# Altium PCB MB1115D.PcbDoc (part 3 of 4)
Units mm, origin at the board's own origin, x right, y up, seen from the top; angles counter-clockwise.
Board outline 66 x 97 mm, 2 copper layers (TOP, Bottom), stack 1.535 mm thick; 198 components, 186 nets, 760 pads, 493 vias.
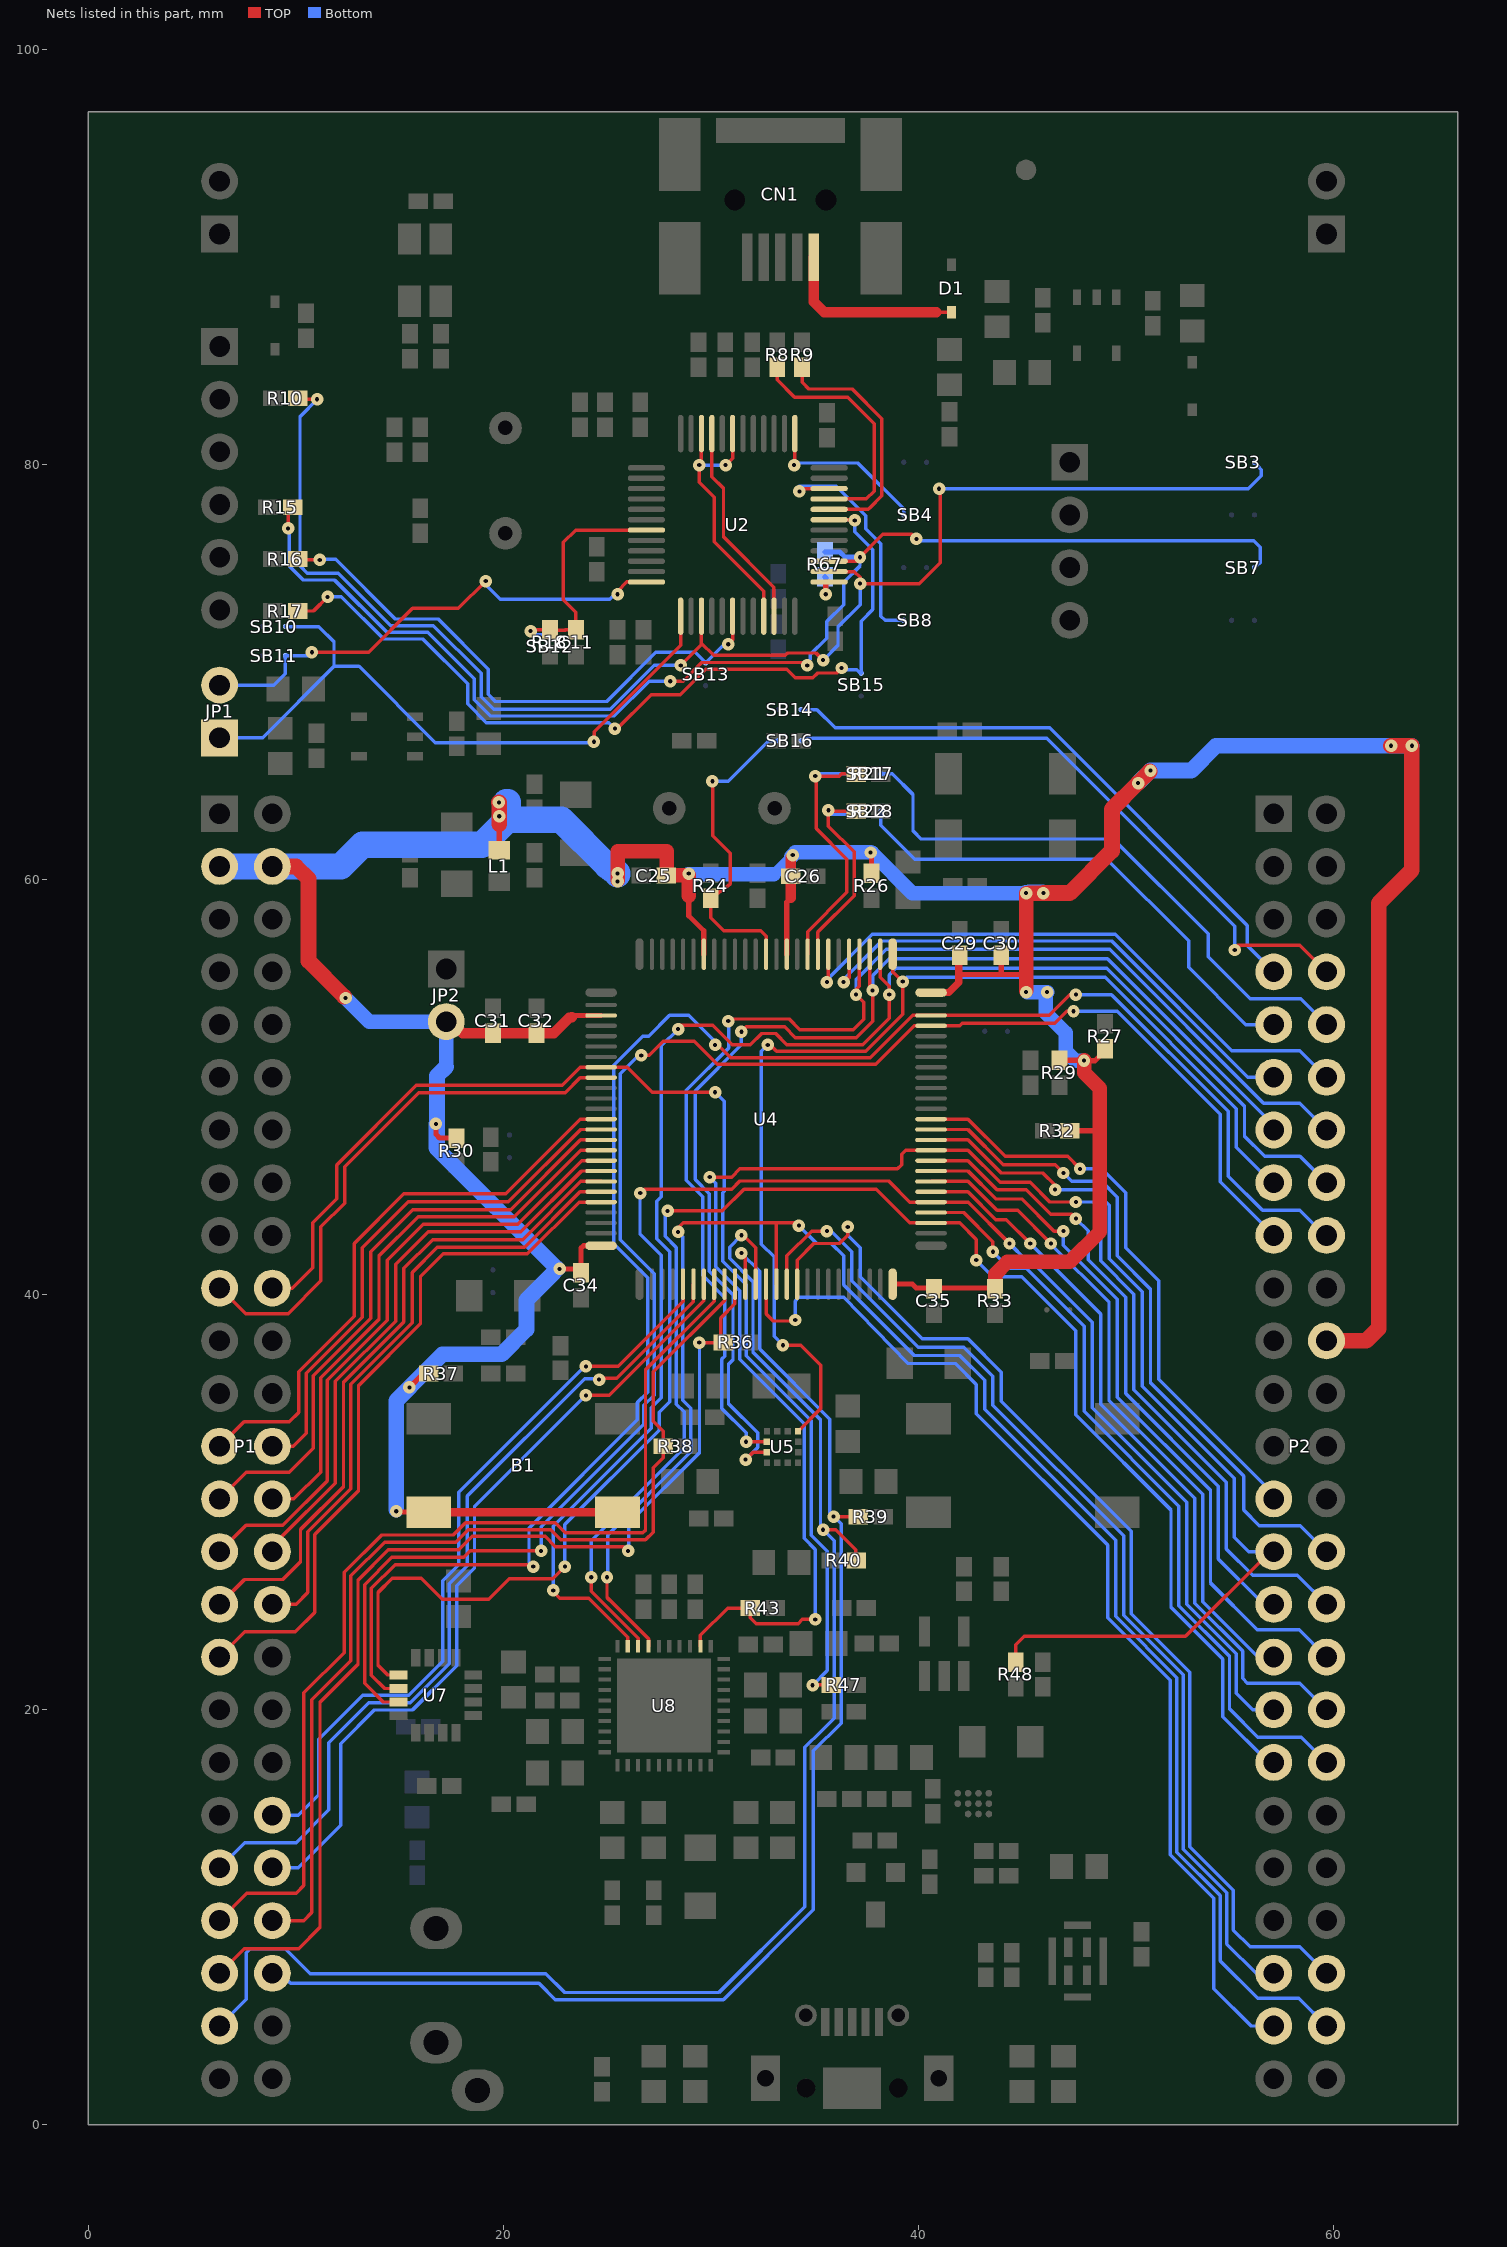
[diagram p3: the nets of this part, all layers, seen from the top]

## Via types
v1: diameter 0.6, hole 0.2, TOP to Bottom, tented both sides, 492 vias
v2: diameter 0.6, hole 0.2, TOP to Bottom, tented bottom, 1 vias

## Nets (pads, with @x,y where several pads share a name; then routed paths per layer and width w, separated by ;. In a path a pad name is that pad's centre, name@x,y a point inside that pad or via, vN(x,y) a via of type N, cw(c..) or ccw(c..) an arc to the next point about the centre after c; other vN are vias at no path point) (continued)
PC4: P1.20 R47.2 U4.33 | length 60.6
  TOP w0.165: P1.20@8.87,40.32 9.823,40.32 10.811,41.309 10.811,43.469 11.969,44.626 11.969,46.251 15.804,50.086 22.84,50.086 23.716,50.962 U4.33@24.714,50.962 25.965,50.962 27.171,49.756 v1(30.206,49.756) ; v1(34.905,21.181) 34.905,21.2 R47.2@35.8,21.2
  Bottom w0.165: v1(30.206,49.756) 30.219,49.756 30.651,49.324 30.651,44.981 30.574,44.905 30.574,41.615 31.717,40.472 31.717,37.056 34.842,33.932 34.842,28.407 35.616,27.633 35.616,21.892 v1(34.905,21.181)
PC5: P1.19 U4.34 | length 26.2
  TOP w0.165: P1.19@6.33,40.32 7.579,39.088 9.632,39.088 11.211,40.667 11.211,43.269 12.35,44.408 12.35,46.175 15.919,49.743 22.98,49.743 23.698,50.462 U4.34@24.714,50.462
PC6: P2.47 U4.63 | length 52
  TOP w0.165: U4.63@32.664,40.512 32.664,39.071 33,38.735 34.018,38.735 v1(34.067,38.783)
  Bottom w0.165: v1(34.067,38.783) 34.067,39.698 34.24,39.871 36.398,39.871 39.5,36.7 41.796,36.672 42.795,35.673 42.795,34.274 49.129,27.94 49.129,24.433 52.139,21.423 52.139,13.015 54.234,10.919 54.234,6.563 56.038,4.76 P2.47@57.13,4.76
PC7: P2.48 U4.64 U8.37 | length 84.1
  TOP w0.165: v1(24.999,26.388) 24.999,25.41 25.266,25.143 27,23.409 27,23.251 U8.37@27,23.07 ; v1(28.428,43.025) 28.225,43.025 28.669,43.469 33.164,43.469 ; U4.64@33.164,40.512 33.164,43.469 ; v1(34.245,43.33) 34.105,43.469 33.164,43.469
  Bottom w0.165: v1(24.999,26.388) 24.999,26.515 25.024,26.54 25.024,28.42 29.038,32.433 29.038,34.529 28.657,34.91 28.657,42.796 v1(28.428,43.025) ; v1(34.245,43.33) 35.105,42.469 35.799,42.469 36.398,41.87 36.398,40.471 39.797,37.072 41.995,37.072 43.195,35.873 43.195,34.474 49.51,28.158 49.51,24.498 52.456,21.551 52.456,13.143 54.552,11.047 54.552,7.891 56.355,6.088 58.342,6.088 P2.48@59.67,4.76
PC8: P2.45 U4.65 | length 50.4
  TOP w0.165: U4.65@33.664,40.512 33.664,41.87 34.863,43.069 v1(35.599,43.069)
  Bottom w0.165: v1(35.599,43.069) 35.799,43.069 36.798,42.07 36.798,40.67 39.996,37.472 42.195,37.472 43.595,36.073 43.595,34.674 49.891,28.377 49.891,24.562 52.774,21.679 52.774,13.271 54.869,11.175 54.869,8.71 56.279,7.3 P2.45@57.13,7.3
PC9: P2.46 U4.66 | length 52.7
  TOP w0.165: U4.66@34.164,40.512 34.164,41.67 34.963,42.469 36.198,42.469 36.598,42.869 v1(36.598,43.269)
  Bottom w0.165: v1(36.598,43.269) 36.598,42.869 37.198,42.27 37.198,40.87 40.196,37.872 42.395,37.872 43.994,36.273 43.994,34.873 50.272,28.596 50.272,24.627 53.091,21.807 53.091,13.399 55.187,11.303 55.187,9.384 55.988,8.583 58.387,8.583 P2.46@59.67,7.3
PC10: P2.37 U4.78 U8.38 | length 72.6
  TOP w0.165: v1(24.237,26.388) 24.237,25.715 26.5,23.452 U8.38@26.5,23.07 ; v1(27.92,44.041) 30.56,44.041 31.601,45.082 37.976,45.082 39.597,43.462 U4.78@40.614,43.462 41.995,43.462 42.795,42.662 v1(42.795,41.67)
  Bottom w0.165: v1(24.237,26.388) 24.237,28.153 25.075,28.991 28.72,32.636 28.72,34.351 28.339,34.732 28.339,42.276 27.806,42.809 27.806,43.965 27.882,44.041 v1(27.92,44.041) ; v1(42.795,41.67) 43.595,40.87 44.994,40.87 47.593,38.272 47.593,34.211 52.177,29.627 52.177,24.949 54.679,22.447 54.679,19.657 56.876,17.46 P2.37@57.13,17.46
PC11: P2.38 U4.79 | length 37
  TOP w0.165: U4.79@40.614,43.962 42.195,43.962 43.595,42.563 v1(43.595,42.07)
  Bottom w0.165: v1(43.595,42.07) 44.394,41.27 45.194,41.27 47.992,38.472 47.992,34.383 52.558,29.817 52.558,25.013 54.996,22.575 54.996,20.053 56.368,18.682 58.448,18.682 P2.38@59.67,17.46
PC12: P2.35 U4.80 U8.39 | length 74.5
  TOP w0.165: v1(22.405,25.753) 22.405,25.678 22.711,25.372 24.123,25.372 26,23.495 U8.39@26,23.07 ; v1(26.6,44.9) 26.782,45.082 31.001,45.082 31.401,45.482 38.576,45.482 39.597,44.462 U4.80@40.614,44.462 42.402,44.462 v1(44.394,42.469)
  Bottom w0.165: v1(22.405,25.753) 22.405,28.836 27.133,33.563 27.133,34.554 27.615,35.037 27.615,41.907 26.587,42.936 26.587,44.887 v1(26.6,44.9) ; v1(44.394,42.469) 45.194,41.67 45.394,41.67 48.392,38.671 48.392,34.554 52.939,30.008 52.939,25.078 55.314,22.703 55.314,20.8 56.114,20 P2.35@57.13,20
PC13: P2.12 U4.7 | length 29.3
  TOP w0.165: v1(35.599,55.063) 35.664,55.128 U4.7@35.664,56.412
  Bottom w0.165: v1(35.599,55.063) 35.599,55.174 37.788,57.363 49.497,57.363 55.098,51.763 58.387,51.763 P2.12@59.67,50.48
PC14: P2.9 SB18.2 | length 24.3
  Bottom w0.165: SB18.2@38.2,63.3 38.2,62.615 39.82,60.995 49.091,60.995 53.028,57.058 53.028,55.78 55.788,53.02 P2.9@57.13,53.02
PC14-OSC32_IN: R22.1 SB18.1 U4.8 | length 11.2
  TOP w0.165: U4.8@35.164,56.412 35.164,57.482 36.912,59.23 36.912,61.338 35.667,62.583 v1(35.667,63.345) 35.712,63.3 R22.1@37,63.3
  Bottom w0.165: v1(35.667,63.345) 35.667,63.154 36.954,63.154 SB18.1@37.1,63.3
PC15: P2.10 SB17.2 | length 28.1
  Bottom w0.165: SB17.2@38.2,65.1 38.751,65.1 39.744,64.107 39.744,62.367 40.15,61.961 49.408,61.961 53.968,57.401 53.968,56.284 55.988,54.263 58.427,54.263 P2.10@59.67,53.02
PC15-OSC32_OUT: R21.1 SB17.1 U4.9 | length 14.2
  TOP w0.165: U4.9@34.664,56.412 34.664,57.503 36.556,59.395 36.556,60.995 35.083,62.469 v1@35.083,64.983 ; v1(35.032,64.996) 35.083,64.996 v1@35.083,64.983 ; R21.1@37,65.1 36.298,65.1 36.181,64.983 v1@35.083,64.983
  Bottom w0.165: v1(35.032,64.996) 35.032,65.1 SB17.1@37.1,65.1
PD0: P2.36 U4.81 | length 35.7
  TOP w0.165: U4.81@40.614,44.962 42.395,44.962 43.741,43.616 44.247,43.616 v1(45.394,42.469)
  Bottom w0.165: v1(45.394,42.469) 48.792,39.071 48.792,34.726 53.32,30.198 53.32,25.142 55.631,22.831 55.631,21.51 55.86,21.282 58.388,21.282 P2.36@59.67,20
PD1: P2.33 U4.82 | length 31.8
  TOP w0.165: U4.82@40.614,45.462 42.395,45.462 43.791,44.066 44.797,44.066 v1(46.393,42.469)
  Bottom w0.165: v1(46.393,42.469) 46.393,42.433 49.192,39.635 49.192,34.898 53.701,30.389 53.701,25.207 56.292,22.616 57.054,22.616 P2.33@57.13,22.54
PD2: P2.34 U4.83 | length 34.5
  TOP w0.165: U4.83@40.614,45.962 42.395,45.962 43.742,44.615 44.994,44.615 46.54,43.069 v1(46.993,43.069)
  Bottom w0.165: v1(46.993,43.069) 46.993,42.38 49.592,39.781 49.592,35.069 54.082,30.579 54.082,26.109 56.34,23.851 58.359,23.851 P2.34@59.67,22.54
PD3: P2.31 U4.84 | length 31
  TOP w0.165: U4.84@40.614,46.462 42.395,46.462 43.792,45.065 45.194,45.065 46.39,43.869 47.393,43.869 v1(47.593,43.669)
  Bottom w0.165: v1(47.593,43.669) 48.185,43.076 48.185,41.691 49.991,39.885 49.991,35.241 54.463,30.77 54.463,27.264 56.647,25.08 P2.31@57.13,25.08
PD4: P2.32 R43.1 U4.85 U8.32 | length 76.3
  TOP w0.165: U8.32@29.5,23.07 29.5,23.581 30.819,24.9 R43.1@31.9,24.9 31.9,24.44 32.187,24.153 34.207,24.153 34.41,24.356 v1(35.032,24.356) ; v1(29.952,45.668) 31.001,45.668 31.401,46.068 38.997,46.068 39.197,46.268 39.197,46.762 39.397,46.962 U4.85@40.614,46.962 42.395,46.962 43.942,45.415 45.394,45.415 46.341,44.468 v1(47.593,44.468)
  Bottom w0.165: v1(29.952,45.668) 30.244,45.376 30.244,41.349 31.4,40.193 31.4,36.891 34.499,33.792 34.499,28.255 35.032,27.721 v1(35.032,24.356) ; v1(47.593,44.468) 48.431,44.468 48.792,44.107 48.792,41.628 50.391,40.029 50.391,35.413 54.844,30.96 54.844,27.748 56.114,26.478 58.272,26.478 P2.32@59.67,25.08
PD5: P2.29 R48.2 U4.86 | length 45.8
  TOP w0.165: U4.86@40.614,47.462 42.395,47.462 43.992,45.865 45.993,45.865 46.591,45.268 v1(46.593,45.068) ; R48.2@44.7,22.3 44.7,23.14 45.103,23.543 52.876,23.543 56.952,27.62 P2.29@57.13,27.62
  Bottom w0.165: v1(46.593,45.068) 48.431,45.068 49.192,44.307 49.192,41.742 50.791,40.143 50.791,35.585 55.225,31.151 55.225,28.319 55.924,27.62 P2.29@57.13,27.62
PD6: P2.30 U4.87 | length 32.7
  TOP w0.165: U4.87@40.614,47.962 42.395,47.962 44.09,46.268 46.593,46.268 v1(46.993,45.868)
  Bottom w0.165: v1(46.993,45.868) 47.393,45.468 48.83,45.468 49.592,44.706 49.592,41.87 51.191,40.271 51.191,35.756 55.681,31.266 55.681,29.626 56.432,28.876 58.414,28.876 P2.30@59.67,27.62
PD7: P2.27 U4.88 | length 28.6
  TOP w0.165: U4.88@40.614,48.462 42.395,48.462 44.19,46.667 47.193,46.667 v1(47.792,46.068)
  Bottom w0.165: v1(47.792,46.068) 48.848,46.068 49.991,44.925 49.991,42.27 51.591,40.67 51.591,35.928 57.13,30.388 P2.27@57.13,30.16
PD8: P1.40 U4.55 | length 36.9
  TOP w0.165: v1(23.983,36.548) 25.532,36.548 28.664,39.679 U4.55@28.664,40.512
  Bottom w0.165: P1.40@8.87,14.92 10.127,14.92 11.105,15.898 11.105,18.577 13.226,20.698 15.447,20.698 17.087,22.339 17.087,26.223 17.849,26.985 17.849,30.477 23.983,36.612 v1(23.983,36.548)
PD9: P1.41 U4.56 | length 41.4
  TOP w0.165: v1(24.618,35.913) 24.669,35.913 v1@24.732,35.976 ; v1@24.682,35.976 v1@24.732,35.976 ; U4.56@29.164,40.512 29.164,39.671 25.469,35.976 v1@24.732,35.976
  Bottom w0.165: P1.41@6.33,12.38 7.549,13.599 10.013,13.599 11.588,15.174 11.588,18.4 13.518,20.33 15.524,20.33 17.404,22.211 17.404,26.07 18.268,26.934 18.268,30.3 23.92,35.951 24.705,35.951 24.705,35.913 v1(24.618,35.913)
PD10: P1.42 U4.57 | length 39.2
  TOP w0.165: v1(23.983,35.151) 25.101,35.151 29.664,39.714 U4.57@29.664,40.512
  Bottom w0.165: P1.42@8.87,12.38 10.115,12.38 12.159,14.425 12.159,18.362 13.785,19.987 15.626,19.987 17.76,22.121 17.76,25.969 18.611,26.82 18.611,29.779 v1(23.983,35.151)
PD11: P1.43 U4.58 | length 49.6
  TOP w0.165: P1.43@6.33,9.84 7.638,11.148 10.013,11.148 10.394,11.529 10.394,20.813 12.337,22.756 12.337,26.617 14.141,28.42 17.595,28.42 18.179,29.004 22.497,29.004 22.98,28.522 26.726,28.522 26.853,28.649 26.853,36.383 30.164,39.693 U4.58@30.164,40.512
PD12: P1.44 R38.2 U4.59 | length 48.7
  TOP w0.165: P1.44@8.87,9.84 10.387,9.84 10.775,10.228 10.775,20.483 12.312,22.019 12.655,22.362 12.655,26.451 14.28,28.077 17.709,28.077 18.306,28.674 22.281,28.674 22.764,28.191 26.853,28.191 27.222,28.56 27.222,31.658 27.7,32.137 R38.2@27.7,32.7 27.7,33.415 27.222,33.894 27.222,36.281 30.664,39.723 U4.59@30.664,40.512
PD13: P1.45 R36.2 U4.60 | length 53.2
  TOP w0.165: P1.45@6.33,7.3 7.517,8.487 10.14,8.487 11.166,9.513 11.166,20.353 12.998,22.184 12.998,26.248 14.458,27.709 17.862,27.709 18.509,28.356 22.015,28.356 22.51,27.861 25.812,27.861 v1(26.015,27.658) ; v1(29.444,37.691) R36.2@30.473,37.691 ; R36.2@30.6,37.7 30.591,37.691 R36.2@30.473,37.691 ; U4.60@31.164,40.512 31.164,39.571 30.473,38.88 R36.2@30.473,37.691
  Bottom w0.165: v1(26.015,27.658) 26.053,27.696 26.053,28.979 29.457,32.382 29.457,37.526 29.368,37.615 v1(29.444,37.691)
PD14: P1.46 R39.2 U4.61 | length 65.4
  TOP w0.165: v1(31.476,42.009) 31.462,42.009 31.469,42.002 31.664,41.807 U4.61@31.664,40.512 ; v1(35.921,29.309) 35.934,29.309 35.943,29.3 R39.2@37.1,29.3
  Bottom w0.165: P1.46@8.87,7.3 9.264,7.3 9.746,6.817 21.722,6.817 22.51,6.03 30.612,6.03 34.943,10.361 34.943,18.026 36.277,19.36 36.277,28.953 v1(35.921,29.309) 35.738,29.492 35.738,34.001 32.352,37.386 32.352,37.424 32.352,41.133 v1(31.476,42.009)
PD15: P1.47 R40.2 U4.62 | length 74.1
  TOP w0.165: v1(31.476,42.869) 31.564,42.869 32.164,42.27 U4.62@32.164,40.512 ; v1(35.413,28.674) 36.023,28.674 36.988,27.709 36.988,27.2 R40.2@37,27.2
  Bottom w0.165: P1.47@6.33,4.76 7.613,6.043 7.613,8.287 7.813,8.487 9.499,8.487 10.699,7.287 22.053,7.287 22.967,6.373 30.396,6.373 34.537,10.513 34.537,18.184 35.324,18.971 35.946,19.593 35.946,28.141 v1(35.413,28.674) 35.286,28.801 35.286,29.093 35.286,33.983 32.035,37.234 32.035,40.625 30.905,41.755 30.905,42.298 v1(31.476,42.869)
PE0: P2.17 U4.97 U7.7 | length 81.9
  TOP w0.165: U7.7@14.95,20.375 14.223,20.375 13.315,21.283 13.315,26.032 14.623,27.34 18.09,27.34 18.408,27.658 v1(21.824,27.658) ; v1(26.65,51.534) 27.031,51.534 27.704,52.207 28.822,52.207 29.203,52.207 30.308,51.102 37.953,51.102 39.813,52.962 U4.97@40.614,52.962 41.995,52.962 42.117,53.083 46.566,53.083 47.147,53.664 v1(47.478,53.664)
  Bottom w0.165: v1(21.824,27.658) 21.824,28.814 26.777,33.767 26.777,34.668 27.272,35.164 27.272,41.018 25.647,42.644 25.647,50.645 26.536,51.534 v1(26.65,51.534) ; v1(47.478,53.664) 49.59,53.664 54.552,48.702 54.552,45.438 P2.17@57.13,42.86
PE1: P2.18 U4.98 U7.6 | length 85.9
  TOP w0.165: U7.6@14.95,21.025 14.284,21.025 13.645,21.664 13.645,25.855 14.788,26.998 21.392,26.998 21.494,26.896 v1(21.443,26.896) ; v1(30.206,52.042) 30.206,52.169 30.955,51.42 37.686,51.42 39.728,53.462 U4.98@40.614,53.462 46.307,53.462 47.309,54.463 v1(47.593,54.463)
  Bottom w0.165: v1(21.443,26.896) 21.24,26.896 21.24,28.75 26.46,33.97 26.46,34.808 26.955,35.303 26.955,40.815 25.317,42.453 25.317,51.064 26.714,52.461 27.006,52.461 28.009,53.464 28.936,53.464 30.206,52.194 v1(30.206,52.042) ; v1(47.593,54.463) 49.311,54.463 54.939,48.835 54.939,45.717 56.588,44.069 58.387,44.069 59.596,42.86 P2.18@59.67,42.86
PE2: P2.15 U4.1 U5.7 | length 54.6
  TOP w0.165: v1(32.746,52.042) 32.746,52.067 32.835,52.067 33.165,51.737 37.47,51.737 39.248,53.515 v1(39.248,55.09) 38.791,55.547 38.764,55.547 U4.1@38.764,56.412 ; v1(33.477,37.567) 34.341,37.567 35.298,36.609 35.298,34.519 U5.7@34.206,33.426
  Bottom w0.165: v1(32.746,52.042) 32.441,51.737 32.441,42.441 33.051,41.831 33.051,37.993 v1(33.477,37.567) ; v1(39.248,55.09) 39.452,55.293 49.002,55.293 55.327,48.969 55.327,47.102 57.028,45.4 P2.15@57.13,45.4
PE3: P2.16 U4.2 U7.5 | length 86
  TOP w0.165: U7.5@14.95,21.675 14.434,21.675 13.963,22.146 13.963,25.651 14.649,26.337 16.046,26.337 17.062,25.321 19.297,25.321 20.287,26.312 22.383,26.312 v1(22.967,26.896) ; v1(28.428,52.804) 28.428,52.982 29.266,52.982 30.092,52.982 31.032,52.042 31.908,52.042 32.454,52.588 33.127,52.588 33.66,52.055 37.318,52.055 38.597,53.334 v1(38.597,54.463) 38.597,54.863 38.164,55.297 U4.2@38.164,56.412
  Bottom w0.165: v1(22.967,26.896) 22.967,28.928 27.514,33.475 27.514,34.338 28.022,34.846 28.022,42.072 27.387,42.707 27.387,44.498 27.615,44.727 27.615,51.991 v1(28.428,52.804) ; v1(38.597,54.463) 38.597,55.408 38.914,55.725 49.078,55.725 55.72,49.083 55.72,47.64 56.686,46.675 58.395,46.675 P2.16@59.67,45.4
PE4: P2.13 U4.3 U5.12 | length 58.6
  TOP w0.165: v1(31.476,52.677) 31.705,52.906 33.559,52.906 34.08,52.385 37.001,52.385 37.798,53.182 v1(37.798,54.663) 37.664,54.663 U4.3@37.664,56.412 ; v1(31.674,32.055) 32.033,32.414 U5.12@32.693,32.414
  Bottom w0.165: v1(31.476,52.677) 31.476,52.055 29.241,49.819 29.241,45.552 29.927,44.866 29.927,41.133 31.07,39.99 31.07,36.865 30.854,36.65 30.854,34.745 32.258,33.34 32.258,32.639 v1(31.674,32.055) ; v1(37.798,54.663) 37.798,55.383 38.597,56.182 49.116,56.182 57.13,48.168 P2.13@57.13,47.94
PE5: P2.14 U4.4 U5.11 | length 61.4
  TOP w0.165: v1(30.841,53.185) 30.841,53.287 33.787,53.287 34.295,52.779 36.874,52.779 37.369,53.274 37.369,54.093 v1(36.998,54.463) 36.998,54.698 37.164,54.863 U4.4@37.164,56.412 ; v1(31.699,32.918) 31.704,32.914 U5.11@32.693,32.914
  Bottom w0.165: v1(30.841,53.185) 30.866,53.185 30.866,51.891 28.822,49.846 28.822,45.514 29.609,44.727 29.609,40.929 30.676,39.863 30.676,37.043 30.536,36.904 30.536,34.516 31.699,33.353 v1(31.699,32.918) ; v1(36.998,54.463) 36.998,55.189 38.448,56.639 49.218,56.639 56.634,49.223 58.387,49.223 P2.14@59.67,47.94
PE6: P2.11 U4.5 | length 25.9
  TOP w0.165: v1(36.398,55.063) 36.598,55.263 36.664,55.263 U4.5@36.664,56.412
  Bottom w0.165: v1(36.398,55.063) 36.398,55.212 38.232,57.046 49.319,57.046 55.885,50.48 P2.11@57.13,50.48
PE7: P1.25 U4.38 | length 28.1
  TOP w0.165: P1.25@6.33,32.7 7.504,33.874 9.683,33.874 10.134,34.325 10.134,36.044 10.134,36.285 12.81,38.96 12.81,42.47 15.207,44.866 20.122,44.866 23.718,48.462 U4.38@24.714,48.462
PE8: P1.26 U4.39 | length 25.8
  TOP w0.165: P1.26@8.87,32.7 9.873,32.7 10.508,33.335 10.508,36.213 13.21,38.915 13.21,42.27 15.413,44.473 20.237,44.473 23.726,47.962 U4.39@24.714,47.962
PE9: P1.27 U4.40 | length 29.5
  TOP w0.165: P1.27@6.33,30.16 7.613,31.443 9.683,31.443 10.839,32.599 10.839,36.098 13.61,38.869 13.61,42.07 15.645,44.104 20.364,44.104 23.721,47.462 U4.40@24.714,47.462
PE10: P1.28 U4.41 | length 27.3
  TOP w0.165: P1.28@8.87,30.16 9.899,30.16 11.194,31.455 11.194,36.008 14.01,38.823 14.01,41.87 15.901,43.762 20.529,43.762 23.729,46.962 U4.41@24.714,46.962
PE11: P1.29 U4.42 | length 30.7
  TOP w0.165: P1.29@6.33,27.62 7.6,28.89 9.378,28.89 11.512,31.023 11.512,35.88 14.41,38.778 14.41,41.67 16.133,43.393 20.706,43.393 23.775,46.462 U4.42@24.714,46.462
PE12: P1.30 U4.43 | length 28.1
  TOP w0.165: P1.30@8.87,27.62 8.908,27.62 9.213,27.925 9.213,28.229 11.905,30.922 11.905,35.828 14.809,38.732 14.809,41.47 16.377,43.038 20.846,43.038 23.77,45.962 U4.43@24.714,45.962
PE13: P1.31 U4.44 | length 32.2
  TOP w0.165: P1.31@6.33,25.08 7.528,26.278 9.369,26.278 10.229,27.137 10.229,28.687 12.299,30.757 12.299,35.776 15.209,38.686 15.209,41.27 16.596,42.657 20.935,42.657 23.74,45.462 U4.44@24.714,45.462
PE14: P1.32 U4.45 | length 30.2
  TOP w0.165: P1.32@8.87,25.08 10.013,25.08 10.585,25.651 10.585,28.572 12.655,30.642 12.655,35.686 15.609,38.641 15.609,41.07 16.827,42.288 21.024,42.288 23.697,44.962 U4.45@24.714,44.962
PE15: P1.33 U4.46 | length 34
  TOP w0.165: P1.33@6.33,22.54 7.541,23.751 9.98,23.751 10.915,24.686 10.915,28.445 13.023,30.554 13.023,35.609 16.009,38.595 16.009,40.87 17.109,41.971 21.164,41.971 23.655,44.462 U4.46@24.714,44.462
PH0: P2.7 SB14.2 | length 28.6
  Bottom w0.165: SB14.2@34.35,68.2 35.117,68.2 35.997,67.32 46.335,67.32 55.86,57.795 55.86,56.83 P2.7@57.13,55.56
PH1: P2.8 SB16.2 | length 30.9
  TOP w0.165: v1(55.25,56.614) 55.403,56.766 55.403,56.843 58.387,56.843 P2.8@59.67,55.56
  Bottom w0.165: SB16.2@34.35,66.7 34.473,66.7 34.585,66.812 46.195,66.812 55.25,57.757 v1(55.25,56.614)
PH1-OSC_OUT: R24.2 SB16.1 U4.13 | length 15.3
  TOP w0.165: v1(30.079,64.742) 30.092,64.742 30.092,62.126 30.943,61.275 30.943,59.793 R24.2@30,59.1 30,58.166 30.625,57.541 32.403,57.541 32.664,57.281 U4.13@32.664,56.412
  Bottom w0.165: v1(30.079,64.742) 30.841,64.742 32.799,66.7 SB16.1@33.25,66.7
STLINK_RX: JP1.1 SB10.2 U2.13 | length 32.6
  TOP w0.165: v1(24.364,66.647) 24.377,66.647 24.377,67.13 28.55,71.303 U2.13@28.55,72.7
  Bottom w0.165: JP1.1@6.33,66.837 8.4,66.837 11.842,70.279 11.842,70.292 ; SB10.2@9.5,72.2 11.102,72.2 11.842,71.46 11.842,70.292 ; v1(24.364,66.647) 24.364,66.609 16.731,66.609 13.048,70.292 11.842,70.292
STLINK_TX: JP1.2 SB11.2 U2.12 | length 24.2
  TOP w0.165: v1(10.775,70.965) 13.516,70.965 15.625,73.073 17.836,73.073 v1(19.157,74.394) ; v1(25.507,73.759) 25.507,73.899 25.958,74.35 U2.12@26.9,74.35
  Bottom w0.165: JP1.2@6.33,69.377 8.946,69.377 9.5,69.931 SB11.2@9.5,70.8 10.61,70.8 v1(10.775,70.965) ; v1(19.157,74.394) 19.157,74.216 19.856,73.518 25.139,73.518 25.507,73.886 v1(25.507,73.759)
STM_JTCK: SB4.2 U2.37 | length 8.1
  TOP w0.165: v1(34.016,79.982) 34.016,80.033 34.05,80.067 U2.37@34.05,81.5
  Bottom w0.165: v1(34.016,79.982) 34.118,80.084 37.089,80.084 39.299,77.874 39.299,77.599 SB4.2@39.299,77.581
STM_JTMS: SB8.2 U2.34 | length 11.9
  TOP w0.165: v1(34.27,78.712) 34.408,78.85 U2.34@35.7,78.85
  Bottom w0.165: v1(34.27,78.712) 34.27,78.966 36.048,78.966 37.47,77.544 37.47,76.909 38.197,76.182 38.197,72.701 38.398,72.5 SB8.2@39.299,72.501
STM_RST: C11.2 R18.1 SB12.2 U2.7 | length 12
  TOP w0.165: v1(21.316,71.981) 21.316,72.05 R18.1@22.215,72.05 ; R18.1@22.25,72.05 R18.1@22.215,72.05 ; U2.7@26.9,76.85 26.9,76.845 23.488,76.845 22.896,76.253 22.896,73.487 23.5,72.883 C11.2@23.5,72.05 22.992,72.05 22.992,72.032 22.267,72.032 22.25,72.015 R18.1@22.215,72.05
  Bottom w0.165: v1(21.316,71.981) 21.497,71.8 SB12.2@22.25,71.8
SWIM: U2.22 U2.45 | length 10
  TOP w0.165: U2.45@30.05,81.5 30.05,79.425 30.613,78.862 30.613,76.527 33.041,74.099 33.041,72.959 U2.22@33.05,72.7
SWIM_IN: U2.21 U2.43 U2.46 | length 13.1
  TOP w0.165: U2.46@29.55,81.5 29.55,80.452 29.55,80.088 v1(29.444,79.982) 29.444,79.157 30.175,78.425 30.175,76.28 32.55,73.905 U2.21@32.55,72.7 ; v1(30.714,79.982) 31.05,80.318 U2.43@31.05,81.5
  Bottom w0.165: v1(29.444,79.982) v1(30.714,79.982)
T_JTCK: R10.2 SB3.1 U2.15 U2.26 | length 72
  TOP w0.165: R10.2@10.1,83.2 10.143,83.157 v1(11.029,83.157) ; v1(28.555,70.33) 29.55,71.325 29.55,71.405 ; U2.15@29.55,72.7 29.55,71.625 29.55,71.405 ; v1(35.413,70.584) 35.07,70.927 33.711,70.927 33.597,70.813 30.143,70.813 29.55,71.405 ; U2.26@35.7,74.85 36.92,74.85 37.198,74.572 v1(37.198,74.267) 40.049,74.267 41.065,75.283 41.065,78.839 v1(41.001,78.839)
  Bottom w0.165: v1(11.029,83.157) 11.029,83.144 10.204,82.319 10.204,75.131 10.559,74.775 12.045,74.775 14.572,72.248 16.63,72.248 18.928,69.949 18.928,68.819 19.538,68.209 25.151,68.209 27.272,70.33 v1(28.555,70.33) ; v1(35.413,70.584) 36.129,71.3 36.129,72.184 37.198,73.254 v1(37.198,74.267) ; v1(41.001,78.839) 55.911,78.839 56.533,79.461 56.533,79.767 SB3.1@56.199,80.121
T_JTMS: R15.2 R67.2 SB7.1 U2.27 | length 63.5
  TOP w0.165: v1(9.632,76.934) 9.632,77.95 R15.2@9.85,77.95 ; v1(28.047,69.568) 28.669,69.568 29.571,70.47 34.372,70.47 34.518,70.324 34.524,70.33 v1(34.651,70.33) ; U2.27@35.7,75.35 37.004,75.35 v1(37.191,75.537) 38.296,76.642 39.693,76.642 v1(39.909,76.426)
  Bottom w0.165: v1(9.632,76.934) 9.632,76.947 9.683,76.947 9.683,75.118 10.356,74.445 11.867,74.445 14.395,71.917 16.363,71.917 18.598,69.682 18.598,68.666 19.373,67.892 25.355,67.892 27.031,69.568 v1(28.047,69.568) ; v1(34.651,70.33) 34.651,70.487 34.799,70.635 34.799,70.855 35.589,71.645 35.589,72.444 36.398,73.254 36.398,74.325 37.191,75.118 v1(37.191,75.537) ; v1(39.909,76.426) 39.998,76.337 56.165,76.337 56.47,76.032 56.47,75.27 SB7.1@56.199,75.041
  Bottom w0.25: R67.2@35.5,75.8 36.217,75.8 36.48,75.537 v1(37.191,75.537)
T_NRST: R16.2 SB13.1 U2.18 | length 27.4
  TOP w0.165: R16.2@10.1,75.45 10.1,75.41 v1(11.156,75.41) ; v1(30.841,71.346) 31.05,71.555 31.05,72.375 U2.18@31.05,72.7
  Bottom w0.165: v1(11.156,75.41) 11.156,75.448 11.918,75.448 14.801,72.565 16.858,72.565 19.271,70.152 19.271,68.933 19.614,68.59 24.986,68.59 27.349,70.952 29.248,70.952 SB13.1@29.75,70.45 30.646,71.346 v1(30.841,71.346)
T_SWDIO_IN: R67.1 U2.25 | length 1.6
  TOP w0.25: v1(35.54,73.759) 35.54,74.35 U2.25@35.7,74.35
  Bottom w0.25: R67.1@35.5,74.6 35.54,74.56 v1(35.54,73.759)
T_SWO: R17.2 SB15.1 U2.31 | length 41.7
  TOP w0.165: R17.2@10.1,72.95 10.855,72.95 v1(11.537,73.632) ; v1(25.38,67.282) 25.38,67.168 27.133,68.92 28.53,68.92 29.762,70.152 33.66,70.152 34.08,69.733 34.918,69.733 35.146,69.962 36.061,69.962 v1(36.302,70.203) ; U2.31@35.7,77.35 36.937,77.35 v1(36.937,77.315)
  Bottom w0.165: v1(11.537,73.632) 12.197,73.632 14.229,71.6 16.122,71.6 18.281,69.441 18.281,68.476 19.182,67.574 25.088,67.574 v1(25.38,67.282) ; v1(36.302,70.203) 36.302,70.127 37.027,70.127 37.179,69.974 SB15.1@37.25,69.974 ; v1(36.937,77.315) 36.937,76.769 37.813,75.893 37.813,73.022 37.25,72.459 SB15.1@37.25,69.974 ; SB15.1@37.25,69.95 SB15.1@37.25,69.974
U5V: CN1.1 D1.1 | length 9
  TOP w0.165: 40.874,87.357 D1.1@41.6,87.357
  TOP w0.5: CN1.1@34.956,90.001 34.956,87.856 35.464,87.348 40.865,87.348 40.874,87.357
USB_DM: R9.2 U2.32 | length 11.8
  TOP w0.165: R9.2@34.4,84.7 34.4,83.967 34.718,83.648 35.68,83.648 36.808,83.648 38.245,82.211 38.245,78.499 37.674,77.927 37.596,77.85 U2.32@35.7,77.85
USB_DP: R8.2 U2.33 | length 11.7
  TOP w0.165: R8.2@33.2,84.7 33.2,84.084 34.035,83.249 36.598,83.249 37.877,81.97 37.877,78.73 37.497,78.35 U2.33@35.7,78.35
VDD: B1.1 B1.4 C25.2 C26.1 C29.2 C30.2 C31.2 C32.2 C34.2 C35.1 JP2.2 L1.1 P1.3 P1.4 P2.22 R26.1 R27.1 R29.1 R30.1 R32.1 R33.2 R37.2 U4.11 U4.19 U4.28 U4.50 U4.75 U4.100 | length 229.3
  TOP w0.25: v1@14.928,29.563 14.968,29.523 B1.4@16.477,29.523 ; v1(15.474,35.532) 16.142,36.2 R37.2@16.4,36.2 ; v1(16.75,48.232) 16.75,47.731 16.931,47.55 R30.1@17.75,47.55 ; L1.1@19.807,61.422 19.807,62.672 ; v1(22.713,41.247) C34.2@23.75,41.247 ; 23.294,53.375 23.38,53.462 U4.28@24.714,53.462 ; C34.2@23.75,41.05 C34.2@23.75,41.247 ; U4.50@24.714,42.362 23.866,42.362 23.75,42.246 C34.2@23.75,41.247 ; 28.936,59.217 28.936,58.265 29.664,57.537 U4.19@29.664,56.412 ; U4.11@33.664,56.412 33.664,58.929 33.86,59.126 ; v1(37.699,61.313) 37.699,61.288 37.75,61.237 R26.1@37.75,60.3 ; U4.75@38.764,40.512 39.706,40.512 39.898,40.32 C35.1@40.71,40.32 ; C35.1@40.75,40.3 C35.1@40.758,40.32 ; 41.954,55.471 41.992,55.433 44,55.433 ; R33.2@43.7,40.32 C35.1@40.758,40.32 ; C30.2@44,56.35 44,55.433 ; 45.192,55.433 44,55.433 ; R29.1@46.8,51.3 47.999,51.3 48.004,51.3 v1@48.024,51.28 ; R32.1@47.3,47.9 48.721,47.9 48.735,47.914 ; v1(47.986,51.28) 47.999,51.28 v1@48.024,51.28 ; R27.1@49,51.85 49,51.763 48.517,51.28 v1@48.024,51.28 ; C35.1@40.71,40.32 40.518,40.512 40.81,40.512 40.849,40.55 C35.1@40.758,40.32 ; C35.1@40.71,40.32 C35.1@40.758,40.32
  TOP w0.35: U4.100@40.614,54.562 41.463,54.562 41.954,55.052 41.954,55.471 41.954,56.292 41.996,56.335 C29.2@42,56.35
  TOP w0.4: v1(14.839,29.563) v1@14.928,29.563 ; B1.4@16.477,29.523 16.517,29.563 16.568,29.513 B1.1@25.51,29.523
  TOP w0.5: JP2.2@17.25,53.16 17.468,53.171 18.039,52.6 22.426,52.6 23.183,53.356 23.294,53.375 ; C25.2@27.85,60.2 C25.2@27.871,60.221 ; 33.86,59.126 33.86,61.094 v1(33.953,61.186)
  TOP w0.7: v1@25.507,59.98 v1(25.507,60.308) 25.507,61.376 27.871,61.376 27.871,60.221 28.936,60.221 28.936,59.217 ; R33.2@43.7,40.3 43.7,40.32 43.7,40.993 44.297,41.59 47.3,41.59 48.735,43.025 48.735,47.914 48.735,49.959 47.999,50.696 47.999,51.28 v1@47.999,51.3 ; v1@45.192,54.65 45.192,55.433 v1(45.192,59.357)
  TOP w0.762: P1.4@8.87,60.64 10.012,60.64 10.611,60.04 10.611,56.089 v1@12.325,54.375 ; v1(19.792,63.726) 19.807,63.726 v1(19.807,63.059) 19.807,62.672 ; v1@45.344,59.351 v1(46.03,59.357) 47.291,59.353 49.328,61.389 49.328,63.395 v1(50.591,64.658) v1@51.141,65.209 ; P2.22@59.67,37.78 61.585,37.78 62.185,38.38 62.185,58.861 63.784,60.46 v1(63.784,66.457) v1(62.785,66.457)
  Bottom w0.25: v1@22.561,41.285 22.586,41.26 v1@22.586,41.247 ; v1@28.8,60.26 28.936,60.26 v1(28.936,60.297) ; v1@37.572,61.313 37.572,61.376 v1@37.699,61.376
  Bottom w0.5: v1@28.8,60.26 28.8,60.259 v1@28.923,60.259 ; v1@33.876,61.11 33.025,60.259 33.076,60.259 v1@33.953,61.135 ; v1@37.699,61.376 v1@37.788,61.288 ; v1@45.205,59.357 45.205,59.36 45.205,59.387 v1@45.339,59.387 ; v1@46.001,59.387 46.03,59.387 v1(46.03,59.357)
  Bottom w0.508: v1@33.953,61.135 v1(33.953,61.186)
  Bottom w0.7: v1@12.435,54.265 13.54,53.16 JP2.2@17.25,53.16 17.25,50.988 ; v1(16.75,48.232) 16.75,47.096 16.808,47.037 ; v1@28.923,60.259 33.025,60.259 ; v1@33.876,61.11 v1(33.953,61.186) 34.079,61.313 37.572,61.313 v1(37.699,61.313) ; v1@37.788,61.288 39.718,59.357 v1(45.192,59.357) ; v1@45.26,54.582 v1(46.208,54.582) 46.145,54.518 46.145,53.579 47.11,52.613 47.11,51.737 47.567,51.28 v1(47.986,51.28)
  Bottom w0.762: v1@14.839,29.65 14.839,34.884 15.474,35.519 v1(15.474,35.532) 17.074,37.132 19.919,37.132 21.113,38.326 21.113,39.736 22.459,41.082 22.459,41.247 v1@22.586,41.247 ; 17.25,50.988 16.808,50.546 16.808,47.037 v1@22.561,41.285 ; v1@45.205,59.357 v1(45.192,59.357) 45.205,59.36 45.339,59.387 v1@46.001,59.387 ; v1@50.651,64.719 v1(51.191,65.258) 53.15,65.258 54.349,66.457 v1(62.785,66.457) v1(63.784,66.457)
  Bottom w1.27: P1.3@6.33,60.64 P1.4@8.87,60.64 12.172,60.64 13.213,61.681 18.97,61.681 20.173,62.885 ; v1@20.049,62.885 20.173,62.885 ; 20.15,63.726 20.224,63.726 20.224,63.059 ; v1@25.507,60.26 v1(25.507,60.308) 24.984,60.7 22.8,62.885 20.173,62.885
  other v1: 12.4,54.3 45.192,54.582 25.507,59.916
pads on no net: CN1.11 CN1.12 CN5.9 CN5.10 CN5.11 CN5.12 M1.1 P1.35 P1.48 U2.4 U2.11 U2.14 U2.16 U2.17 U2.19 U2.28 U2.38 U2.39 U2.40 U2.41 U2.42 U8.0 U8.4 U8.6 U8.7 U8.9 U8.20 U8.23 U8.24 U8.25 U8.26 U8.36 U9.A2 U9.B1 U9.B2 U9.C2 X3.2 X3.3

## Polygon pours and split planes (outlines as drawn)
GND on Bottom "Template_3" (solid, remove dead copper, pour order 24): 66.04,-0.076 -0.051,-0.076 -0.051,96.977 -0.076,97.003 66.065,97.003
GND on TOP "Template_1" (solid, remove dead copper, pour order 30): 66,0.025 0.076,0.025 0.051,0 0.051,97.028 65.873,97.028 66,96.901

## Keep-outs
Keep-Out Layer:
  the board outline again, w0.254

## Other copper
TOP:
  pour cut-out: 28.042,12.497 28.575,12.497 28.575,12.802 28.573,12.8 28.047,12.8
  pour cut-out: 20.803,18.085 20.803,17.755 20.805,17.752 20.93,17.752 20.93,18.085
  pour cut-out: 36.957,37.996 36.957,37.643 37.389,37.643 37.389,37.668 37.389,37.996
  pour cut-out: 35.907,30.179 35.907,29.824 35.992,29.824 35.992,30.171 35.984,30.179
  pour cut-out: 35.103,28.219 35.103,27.94 35.027,27.94 35.001,27.965 35.027,27.991 35.027,28.296
  pour cut-out: 28.105,4.14 28.41,4.14 28.41,4.013 28.13,4.013 28.105,4.039
  pour cut-out: 45.784,7.569 46.041,7.569 46.041,7.366 46.016,7.391 45.784,7.391
  pour cut-out: 35.15,0.26 35.15,0.39 38.48,0.39 38.48,0.27
  pour cut-out: 8.39,68.11 8.39,68.37 10.1,68.37 10.06,68.33 10.1,68.33 10.1,68.11
  pour cut-out: 32.3,38.89 32.55,38.89 32.55,38.17 32.3,38.17
  pour cut-out: 15.33,19.339 15.596,19.339 15.596,18.619 15.33,18.619
  pour cut-out: 17.885,19.3 18.18,19.3 18.18,18.58 17.885,18.58
  pour cut-out: 25.385,43.343 25.651,43.343 25.651,42.623 25.385,42.623
  pour cut-out: 51.965,67.353 52.231,67.353 52.231,66.633 51.965,66.633
  pour cut-out: 28.91,82.43 29.2,82.43 29.2,82.56 28.91,82.56
  pour cut-out: 29.972,30.15 29.972,29.87 30.886,29.87 30.861,29.896 30.861,30.15
  text "TOP LAYER" at -20,-91.8 h2.45
Bottom:
  pour cut-out: 57.15,74.498 57.506,74.498 57.506,74.524 57.506,74.701 57.15,74.701
  pour cut-out: 18.898,27.254 18.898,26.949 19.634,26.949 19.609,26.975 19.609,27.254
  pour cut-out: 6.299,68.25 6.299,67.92 6.426,67.92 6.426,68.224 6.452,68.25
  pour cut-out: 25.603,66.751 26.187,66.751 26.391,66.954 26.365,66.98 25.705,66.98
  pour cut-out: 51.791,60.829 51.791,59.919 52.045,59.665 52.121,59.741 52.121,60.547
  pour cut-out: 34.245,30.582 33.579,30.582 33.553,30.607 33.553,31.013 34.239,31.013
  pour cut-out: 37.033,21.615 37.465,21.615 37.465,21.895 37.033,21.895
  pour cut-out: 16.637,14.284 17.018,14.284 17.018,17.323 16.637,17.323
  pour cut-out: 38.503,79.433 38.297,79.227 38.425,79.1 38.623,79.298
  pour cut-out: 7.24,70.08
  pour cut-out: 43.26,53.462 42.44,53.461 ccw(c42.441,53.21) 42.19,53.21 42.19,52.18 ccw(c42.431,52.18) 42.431,51.939 43.26,51.938
  pour cut-out: 21.488,70.76 21.489,69.94 ccw(c21.74,69.941) 21.74,69.69 22.77,69.69 ccw(c22.77,69.931) 23.011,69.931 23.012,70.76
  pour cut-out: 19.538,46.66 19.539,45.84 ccw(c19.79,45.841) 19.79,45.59 20.82,45.59 ccw(c20.82,45.831) 21.061,45.831 21.062,46.66
  pour cut-out: 40.12,75.773 38.571,75.77 ccw(c38.571,75.52) 38.32,75.519 38.32,74.49 ccw(c38.561,74.49) 38.561,74.249 40.12,74.247
  text "BOTTOM LAYER" at -20,-91.8 h2.45

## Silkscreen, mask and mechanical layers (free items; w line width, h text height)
Top Silk:
  region: 49.25,76.95 50.52,76.95 50.52,80.76 49.25,80.76
  region: 49.25,71.87 50.52,71.87 50.52,75.68 49.25,75.68
  lines w0.2: 10.2,67.9 10.4,68.1 11.8,68.1 12.2,68.5 12.2,68.7 ; 11.6,67.5 11.8,67.5 12.8,68.5 ; 16.8,37.5 17.8,37.5 18.6,36.7 ; 16.8,38.5 18,38.5 18.6,37.9 ; 26.8,35.9 26.8,32.9 27,32.9 ; 27,37.3 27.4,37.3 27.4,34.2 27.6,34.2 ; 34.4,16.7 34.6,16.9 ; 34.7,19.4 35.1,19 37.5,19 ; 34.8,21.7 35.2,22.1 37.4,22.1 ; 39.9,18.6 39.9,19.1
  lines w0.305: 3.8,64.7 ccw(c4,64.7) 4.2,64.7 ; 3.8,64.7 cw(c4,64.7) 4.2,64.7 ; 3.8,64.7 ccw(c4,64.7) 4.2,64.7 ; 3.8,64.7 cw(c4,64.7) 4.2,64.7 ; 4,85.7 ccw(c4.2,85.7) 4.4,85.7 ; 4,85.7 cw(c4.2,85.7) 4.4,85.7 ; 4,85.7 ccw(c4.2,85.7) 4.4,85.7 ; 4,85.7 cw(c4.2,85.7) 4.4,85.7 ; 54.8,64.9 ccw(c55,64.9) 55.2,64.9 ; 54.8,64.9 cw(c55,64.9) 55.2,64.9 ; 54.8,64.9 ccw(c55,64.9) 55.2,64.9 ; 54.8,64.9 cw(c55,64.9) 55.2,64.9 ; 3.553,64.7 ccw(c4,64.7) 4.447,64.7 ccw(c4,64.7) 3.553,64.7 ; 3.6,64.7 ccw(c4,64.7) 4.4,64.7 ccw(c4,64.7) 3.6,64.7 ; 3.753,85.7 ccw(c4.2,85.7) 4.647,85.7 ccw(c4.2,85.7) 3.753,85.7 ; 3.8,85.7 ccw(c4.2,85.7) 4.6,85.7 ccw(c4.2,85.7) 3.8,85.7 ; 54.553,64.9 ccw(c55,64.9) 55.447,64.9 ccw(c55,64.9) 54.553,64.9 ; 54.6,64.9 ccw(c55,64.9) 55.4,64.9 ccw(c55,64.9) 54.6,64.9
  lines w0.508: 44.17,71.87 45.44,71.87 45.44,75.68 44.17,75.68 44.17,71.87 ; 44.17,76.95 45.44,76.95 45.44,80.76 44.17,80.76 44.17,76.95
  text "GND" at 4.1,90.7 h2 r90
  text "GND" at 62.61,90.67 h2 r90
  text "J" at 47.219,90.043 h15.24
  text "COM" at 18.73,89.25 h2
  text "USB ST-LINK" at 26.59,88.38 h2 r90
  text "PWR" at 39.98,83.39 h2 r90
  text "SWD" at 3.8,78.25 h2 r90
  text "ST-LINK" at 43.1,74.29 h2 r90
  text "K" at 54.483,73.533 h15.24
  text "DISCOVERY" at 52.63,73 h2 r90
  text "www.st.com/stm32f4-discovery" at 16.69,68.96 h3
  text "TX" at 2.4,68.61 h2
  text "MB1115D" at 54.889,67.488 h2.6
  text "RX" at 2.47,66.42 h2
  text "GND" at 1.04,63.12 h2
  text "GND" at 10.55,63.13 h2
  text "GND" at 61.53,63.13 h2
  text "GND" at 52.05,63.11 h2
  text "VDD" at 1.04,60.58 h2
  text "5V" at 61.53,60.59 h2
  text "VDD" at 10.5,60.56 h2
  text "5V" at 52.05,60.57 h2
  text "GND" at 1.04,58.04 h2
  text "NRST" at 10.6,58.05 h2
  text "3V" at 61.53,58.05 h2
  text "3V" at 52.05,58.03 h2
  text "PH1" at 61.58,55.54 h2
  text "PC1" at 1.09,55.5 h2
  text "PC0" at 10.6,55.51 h2
  text "PH0" at 52.11,55.5 h2
  text "PC3" at 1.09,52.96 h2
  text "PC2" at 10.6,52.97 h2
  text "PC15" at 61.59,52.98 h2
  text "PC14" at 52.11,52.95 h2
  text "Idd" at 16.28,50.47 h2
  text "PA1" at 1.09,50.42 h2
  text "PA0" at 10.6,50.43 h2
  text "PE6" at 52.07,50.44 h2
  text "PC13" at 61.59,50.44 h2
  text "PA3" at 1.09,47.88 h2
  text "PA2" at 10.6,47.89 h2
  text "PE4" at 52.07,47.9 h2
  text "PE5" at 61.59,47.9 h2
  text "PA5" at 1.09,45.34 h2
  text "PA4" at 10.6,45.35 h2
  text "PE2" at 52.07,45.36 h2
  text "PE3" at 61.59,45.36 h2
  text "PA7" at 1.09,42.8 h2
  text "PA6" at 10.6,42.81 h2
  text "PE0" at 52.07,42.82 h2
  text "PE1" at 61.59,42.82 h2
  text "PC5" at 1.09,40.26 h2
  text "PC4" at 10.6,40.27 h2
  text "PB8" at 52.07,40.28 h2
  text "PB9" at 61.59,40.28 h2
  text "PB1" at 1.09,37.72 h2
  text "PB0" at 10.6,37.73 h2
  text "VDD" at 61.49,37.74 h2
  text "BOOT0" at 50.92,37.71 h2
  text "GND" at 1.04,35.18 h2
  text "PB2" at 10.59,35.19 h2
  text "PB6" at 52.07,35.2 h2
  text "PB7" at 61.59,35.2 h2
  text "PE7" at 1.09,32.65 h2
  text "PE8" at 10.59,32.65 h2
  text "PB4" at 52.09,32.65 h2
  text "PB5" at 61.59,32.66 h2
  text "PE9" at 1.09,30.11 h2
  text "PE10" at 10.59,30.11 h2
  text "PD7" at 52.09,30.11 h2
  text "PB3" at 61.59,30.12 h2
  text "PE11" at 1.09,27.57 h2
  text "PE12" at 10.59,27.57 h2
  text "PD5" at 52.09,27.57 h2
  text "PD6" at 61.58,27.57 h2
  text "Reset" at 45.3,26.63 h2
  text "User" at 19.33,26.59 h2
  text "PE13" at 1.09,25.03 h2
  text "PE14" at 10.59,25.03 h2
  text "PD3" at 52.09,25.03 h2
  text "PD4" at 61.58,25.03 h2
  text "PE15" at 1.09,22.49 h2
  text "PB10" at 10.59,22.49 h2
  text "PD1" at 52.09,22.49 h2
  text "PD2" at 61.58,22.49 h2
  text "PB12" at 10.59,19.95 h2
  text "PC12" at 52.09,19.95 h2
  text "PD0" at 61.58,19.95 h2
  text "NC" at 1.09,19.92 h2
  text "PC10" at 52.09,17.41 h2
  text "PC11" at 61.58,17.41 h2
  text "PB13" at 1.09,17.32 h2
  text "PB14" at 10.5,16.95 h2
  text "PB15" at 1.09,14.87 h2
  text "PD8" at 10.59,14.87 h2
  text "PA14" at 52.09,14.87 h2
  text "PA15" at 61.58,14.87 h2
  text "PD9" at 1.09,12.33 h2
  text "PD10" at 10.59,12.33 h2
  text "PA10" at 52.09,12.33 h2
  text "PA13" at 61.58,12.33 h2
  text "PD12" at 10.59,9.79 h2
  text "PA8" at 52.09,9.8 h2
  text "PA9" at 61.58,9.79 h2
  text "PD11" at 1.09,9.72 h2
  text "PD14" at 10.59,7.25 h2
  text "PC8" at 52.09,7.26 h2
  text "PC9" at 61.58,7.25 h2
  text "PD13" at 1.09,7.12 h2
  text "PD15" at 1.09,4.71 h2
  text "NC" at 10.59,4.71 h2
  text "PC6" at 52.09,4.72 h2
  text "PC7" at 61.58,4.71 h2
  text "GND" at 1.09,2.17 h2
  text "GND" at 10.59,2.17 h2
  text "GND" at 52.04,2.17 h2
  text "GND" at 61.53,2.17 h2
  text "USB USER" at 31.51,0.59 h2 r90
  text "SILKSCREEN TOP LAYER" at -20,-91.8 h2.45
Bot Silk:
  region: 54.6,65.3 ccw(c55,65.3) 55.4,65.3 ccw(c55,65.3)
  region: 3.6,85.5 ccw(c4,85.5) 4.4,85.5 ccw(c4,85.5)
  region: 46.8,82.1 ccw(c47.2,82.1) 47.6,82.1 ccw(c47.2,82.1)
  region: 3.517,65.25 ccw(c3.917,65.25) 4.317,65.25 ccw(c3.917,65.25)
  lines w0.2: 21.787,17.39 46.787,17.39 ; 21.787,17.323 21.787,8.323 46.787,8.323 46.787,17.323 ; 32.379,91.863 57.379,91.863 ; 32.379,91.796 32.379,82.795 57.379,82.795 57.379,91.796 ; 38.299,70.434 41.537,70.434 41.537,81.102 38.299,81.102 38.299,70.434 ; 54.099,70.334 57.338,70.334 57.338,81.002 54.099,81.002 54.099,70.334
  text "CN1" at 34.32,93.75 h1.5
  text "USB ST-LINK" at 28.56,88.2 h2 r270
  text "E" at 20.98,86.843 h15.24
  text "RESERVED" at 42.42,72.71 h2 r270
  text "DEFAULT" at 51.97,72.7 h2 r270
  text "GND" at 4.51,62.64 h2
  text "GND" at 13.948,62.64 h2
  text "GND" at 55.322,62.622 h2
  text "GND" at 64.7,62.632 h2
  text "VDD" at 13.95,60.09 h2
  text "5V" at 55.272,60.082 h2
  text "5V" at 64.7,60.092 h2
  text "VDD" at 4.54,60.07 h2
  text "NRST" at 13.948,57.55 h2
  text "3V" at 55.272,57.542 h2
  text "3V" at 64.7,57.552 h2
  text "GND" at 4.51,57.53 h2
  text "PC1" at 4.46,55.01 h2
  text "PC0" at 13.948,54.992 h2
  text "PH0" at 55.272,55.002 h2
  text "PH1" at 64.7,55.012 h2
  text "PC3" at 4.46,52.46 h2
  text "PC2" at 13.948,52.452 h2
  text "PC14" at 55.272,52.462 h2
  text "PC15" at 64.7,52.472 h2
  text "PA1" at 4.462,49.922 h2
  text "PA0" at 13.948,49.92 h2
  text "PE6" at 55.272,49.922 h2
  text "PC13" at 64.7,49.932 h2
  text "PA3" at 4.462,47.382 h2
  text "PE4" at 55.272,47.382 h2
  text "PE5" at 64.7,47.392 h2
  text "PA2" at 13.948,47.35 h2
  text "PA5" at 4.462,44.842 h2
  text "PE2" at 55.272,44.842 h2
  text "PE3" at 64.7,44.852 h2
  text "PA4" at 13.948,44.82 h2
  text "PA7" at 4.462,42.302 h2
  text "PA6" at 13.948,42.3 h2
  text "PE0" at 55.272,42.302 h2
  text "PE1" at 64.7,42.312 h2
  text "F" at 35,40 h12.7
  text "G" at 48,40 h12.7
  text "PB8" at 55.272,39.762 h2
  text "PB9" at 64.7,39.772 h2
  text "PC5" at 4.43,39.75 h2
  text "PC4" at 13.948,39.75 h2
  text "PB0" at 13.948,37.23 h2
  text "BOOT0" at 55.272,37.222 h2
  text "VDD" at 64.7,37.232 h2
  text "PB1" at 4.44,37.21 h2
  text "PB6" at 55.272,34.682 h2
  text "PB7" at 64.7,34.692 h2
  text "GND" at 4.51,34.66 h2
  text "PB2" at 13.948,34.66 h2
  text "PE7" at 4.48,32.16 h2
  text "PE8" at 13.948,32.152 h2
  text "PB4" at 55.272,32.142 h2
  text "PB5" at 64.7,32.152 h2
  text "PE9" at 4.44,29.6 h2
  text "PD7" at 55.272,29.602 h2
  text "PB3" at 64.7,29.612 h2
  text "PE10" at 13.948,29.59 h2
  text "H" at 26.797,28.677 h12.7
  text "I" at 35.763,27.711 h12.7
  text "C" at 47.955,27.711 h12.7
  text "PE12" at 13.948,27.06 h2
  text "PD5" at 55.272,27.062 h2
  text "PD6" at 64.7,27.072 h2
  text "PE11" at 4.46,27.03 h2
  text "PD3" at 55.272,24.522 h2
  text "PD4" at 64.7,24.532 h2
  text "PE13" at 4.43,24.49 h2
  text "PE14" at 13.948,24.51 h2
  text "PD1" at 55.272,21.982 h2
  text "PD2" at 64.7,21.992 h2
  text "PE15" at 4.46,21.96 h2
  text "PB10" at 13.948,21.962 h2
  text "PC12" at 55.272,19.442 h2
  text "PD0" at 64.7,19.452 h2
  text "NC" at 4.42,19.42 h2
  text "PB12" at 13.948,19.422 h2
  text "PC10" at 55.272,16.902 h2
  text "PC11" at 64.7,16.912 h2
  text "PB14" at 13.948,16.882 h2
  text "PB13" at 4.46,16.83 h2
  text "PB15" at 4.46,14.37 h2
  text "PA14" at 55.272,14.362 h2
  text "PA15" at 64.7,14.372 h2
  text "PD8" at 13.948,14.35 h2
  text "PD9" at 4.46,11.82 h2
  text "PD10" at 13.948,11.83 h2
  text "PA10" at 55.272,11.822 h2
  text "PA13" at 64.7,11.832 h2
  text "PD12" at 13.948,9.3 h2
  text "PA8" at 55.272,9.282 h2
  text "PA9" at 64.7,9.292 h2
  text "PD11" at 4.46,9.21 h2
  text "PD14" at 13.948,6.75 h2
  text "PC8" at 55.272,6.742 h2
  text "PC9" at 64.7,6.752 h2
  text "PD13" at 4.48,6.61 h2
  text "NC" at 13.948,4.21 h2
  text "PC6" at 55.272,4.202 h2
  text "PC7" at 64.7,4.212 h2
  text "PD15" at 4.44,4.19 h2
  text "GND" at 13.948,1.66 h2
  text "GND" at 55.322,1.662 h2
  text "GND" at 64.7,1.672 h2
  text "GND" at 4.52,1.64 h2
  text "USB USER" at 30.12,0.62 h2 r270
  text "SILKSCREEN BOTTOM LAYER" at -20,-91.8 h2.45
Top Paste:
  text "PASTE MASK TOP LAYER" at -20,-91.8 h2.45
Bot Paste:
  text "PASTE MASK BOTTOM LAYER" at -20,-91.8 h2.45
Top Mask:
  text "SOLDER MASK TOP LAYER" at -20,-91.8 h2.45
Bottom Solder:
  text "SOLDER MASK BOTTOM LAYER" at -20,-91.8 h2.45
Board:
  the board outline again, w0.2
Top Assy:
  text "ASSEMBLY TOP LAYER" at -20,-91.8 h2.45
Top ZI:
  lines w0.203: 20.5,-17.3 45.5,-17.3 ; 33,-29.8 33,-4.8
MECH3:
  lines w0.152: 25.2,31.087 39.6,31.087 ; 33.508,23.487 33.508,37.887 ; 29.342,26.9 37.648,26.9 37.648,35.3 29.342,35.3 29.342,26.9
Bot Assy:
  text "ASSEMBLY BOTTOM LAYER" at 85,-91.8 h2.45
User Attributes:
  lines w0.254: 23.475,13.777 32.365,13.777 ; 26.079,7.491 32.365,13.777 ; 26.079,20.063 32.365,13.777 ; 38.651,7.491 32.365,13.777 ; 38.651,20.063 32.365,13.777 ; 41.255,13.777 32.365,13.777 ; 32.365,4.887 cw(c32.365,13.777) 32.365,22.667 ; 32.365,4.887 ccw(c32.365,13.777) 32.365,22.667 ; 32.365,4.887 32.365,13.777 ; 32.365,13.777 32.365,22.667 ; 32.365,8.697 cw(c32.365,13.777) 32.365,18.857 cw(c32.365,13.777) 32.365,8.697
Drill Drawing:
  drawing of 298 lines, arcs and shapes, not listed
  text "PCB SPECIFICATIONS :" at -54.922,156.429 h3
  text "PCB : TYPE 3" at 92.57,156.257 h3
  text "A.   MATERIAL :" at -54.922,152.429 h3
  text "FR-4" at -16.422,152.429 h3
  text "TG-170" at 0.078,152.429 h3
  text "X  TG-150" at 18.328,152.429 h3
  text "TG-140" at 34.328,152.429 h3
  text "ASPECT-RATIO, AXE Z :" at 92.57,150.757 h3
  text "B.   MATERIAL FAMILY :" at -54.922,149.429 h3
  text "N/A" at -16.422,149.429 h3
  text "WHITE" at 3.507,146.481 h3
  text "C.   SOLDERMASK COLOR :" at -54.922,146.429 h3
  text "GREEN" at -16.422,146.429 h3
  text "X  BLUE" at 18.328,146.429 h3
  text "BLACK" at 34.328,146.429 h3
  text "6:1 to 8:1 / LEVEL \"B\"" at 92.589,144.009 h3
  text "D.   SILKSCREEN COLOR :" at -54.922,143.429 h3
  text "X  WHITE" at -16.422,143.429 h3
  text "YELLOW" at 0.078,143.429 h3
  text "BLACK" at 18.328,143.429 h3
  text "Blue ink PANTONE 2955" at 34.328,143.429 h3
  text "E.   SURFACE FINISH :" at -54.922,140.429 h3
  text "X  ENIG" at -16.422,140.429 h3
  text "IMMERSION SILVER" at 0.078,140.429 h3
  text "IMMERSION TIN" at 34.328,140.429 h3
  text "MINIMUM PARAMETERS" at 92.616,138.408 h3
  text "HASL" at -16.422,137.429 h3
  text "HASL (PB-FREE)" at 0.078,137.429 h3
  text "GOLDEN FINGER" at 34.328,137.429 h3
  text "F.   IMPEDANCE CONTROL :" at -54.922,134.429 h3
  text "NO" at -16.422,134.429 h3
  text "X  YES  (SEE IMPEDANCE TABLE FOR DETAIL INFORMATION)" at 0.078,134.429 h3
  text "DEFAULT" at 92.616,132.908 h3
  text "G.   THROUGH VIA :" at -54.922,131.429 h3
  text "PLUG THE VIAS WHICH ARE COVERED WITH SOLDERMASK ONE OR TWO SIDE." at -16.422,131.429 h3
  text "PLUG MATERIAL :" at -16.422,128.429 h3
  text "X  SOLDERMASK" at 9.078,128.429 h3
  text "NON-CONDUCTIVE EPOXY." at 34.328,128.429 h3
  text "TRACKS : 0.127mm           / GAPS : 0.127mm" at 92.616,127.158 h3
  text "H.   STACK-UP :" at -54.922,125.429 h3
  text "SEE LAYER STACK-UP SEQUENCE FOR OVERALL THICKNESS." at -16.422,125.429 h3
  text "Layer" at 9.183,-27.483 h1.52
  text "Name" at 14.848,-27.483 h1.52
  text "Material" at 25.106,-27.483 h1.52
  text "Thickness" at 34.56,-27.483 h1.52
  text "Constant" at 42.443,-27.483 h1.52
  text "Board Layer Stack" at 49.947,-27.483 h1.52
  text "1" at 9.183,-30.531 h1.52
  text "Top Silk" at 14.848,-30.531 h1.52
  text "2" at 9.183,-33.579 h1.52
  text "Top Mask" at 14.848,-33.579 h1.52
  text "Solder Resist" at 25.106,-33.579 h1.52
  text "0.71mil" at 34.56,-33.579 h1.52
  text "3.5" at 42.443,-33.579 h1.52
  text "3" at 9.183,-36.627 h1.52
  text "TOP" at 14.848,-36.627 h1.52
  text "Copper" at 25.106,-36.627 h1.52
  text "1.38mil" at 34.56,-36.627 h1.52
  text "4" at 9.183,-39.675 h1.52
  text "Dielectric 1" at 14.848,-39.675 h1.52
  text "FR-4" at 25.106,-39.675 h1.52
  text "57.68mil" at 34.56,-39.675 h1.52
  text "4.8" at 42.443,-39.675 h1.52
  text "5" at 9.183,-42.723 h1.52
  text "Bottom" at 14.848,-42.723 h1.52
  text "Copper" at 25.106,-42.723 h1.52
  text "1.38mil" at 34.56,-42.723 h1.52
  text "6" at 9.183,-45.771 h1.52
  text "Bottom Solder" at 14.848,-45.771 h1.52
  text "Solder Resist" at 25.106,-45.771 h1.52
  text "0.71mil" at 34.56,-45.771 h1.52
  text "3.5" at 42.443,-45.771 h1.52
  text "7" at 9.183,-48.819 h1.52
  text "Bot Silk" at 14.848,-48.819 h1.52
  text "Symbol" at -31.733,-54.968 h1.83
  text "Count" at -26.198,-54.968 h1.83
  text "Hole Size" at -20.393,-54.968 h1.83
  text "Plated" at -9.01,-54.968 h1.83
  text "Hole Type" at -4.166,-54.968 h1.83
  text "Drill Layer Pair" at 2.941,-54.968 h1.83
  text "Via/Pad" at 12.802,-54.968 h1.83
  text "Pad Shape" at 18.648,-54.968 h1.83
  text "Template" at 26.006,-54.968 h1.83
  text "Description" at 52.233,-54.968 h1.83
  text "Hole Tolerance (+)" at 60.172,-54.968 h1.83
  text "Hole Tolerance (-)" at 72.314,-54.968 h1.83
  text "Hole Length" at 84.168,-54.968 h1.83
  text "Routed Path Length" at 95.488,-54.968 h1.83
  text "2" at -26.198,-56.994 h1.52
  text "0.650mm (25.59mil)" at -20.393,-56.994 h1.52
  text "PTH" at -9.01,-56.994 h1.52
  text "Round" at -4.166,-56.994 h1.52
  text "TOP - Bottom" at 2.941,-56.994 h1.52
  text "Pad" at 12.802,-56.994 h1.52
  text "Rounded" at 18.648,-56.994 h1.52
  text "c105h65z152m110p105" at 26.006,-56.994 h1.52
  text "-" at 84.168,-56.994 h1.52
  text "-" at 95.488,-56.994 h1.52
  text "2" at -26.198,-59.021 h1.52
  text "0.800mm (31.50mil)" at -20.393,-59.021 h1.52
  text "PTH" at -9.01,-59.021 h1.52
  text "Slot" at -4.166,-59.021 h1.52
  text "TOP - Bottom" at 2.941,-59.021 h1.52
  text "Pad" at 12.802,-59.021 h1.52
  text "Rounded" at 18.648,-59.021 h1.52
  text "r220_140h80_160zc152m225_145p220_140" at 26.006,-59.021 h1.52
  text "1.600mm (62.99mil)" at 84.168,-59.021 h1.52
  text "0.800mm (31.50mil)" at 95.488,-59.021 h1.52
  text "2" at -26.198,-61.047 h1.52
  text "0.900mm (35.43mil)" at -20.393,-61.047 h1.52
  text "NPTH" at -9.01,-61.047 h1.52
  text "Round" at -4.166,-61.047 h1.52
  text "TOP - Bottom" at 2.941,-61.047 h1.52
  text "Pad" at 12.802,-61.047 h1.52
  text "Rounded" at 18.648,-61.047 h1.52
  text "(Mixed)" at 26.006,-61.047 h1.52
  text "-" at 84.168,-61.047 h1.52
  text "-" at 95.488,-61.047 h1.52
  text "2" at -26.198,-63.074 h1.52
  text "1.000mm (39.37mil)" at -20.393,-63.074 h1.52
  text "NPTH" at -9.01,-63.074 h1.52
  text "Round" at -4.166,-63.074 h1.52
  text "TOP - Bottom" at 2.941,-63.074 h1.52
  text "Pad" at 12.802,-63.074 h1.52
  text "Rounded" at 18.648,-63.074 h1.52
  text "c90hn100z152m110p90" at 26.006,-63.074 h1.52
  text "-" at 84.168,-63.074 h1.52
  text "-" at 95.488,-63.074 h1.52
  text "3" at -26.198,-65.1 h1.52
  text "1.200mm (47.24mil)" at -20.393,-65.1 h1.52
  text "PTH" at -9.01,-65.1 h1.52
  text "Slot" at -4.166,-65.1 h1.52
  text "TOP - Bottom" at 2.941,-65.1 h1.52
  text "Pad" at 12.802,-65.1 h1.52
  text "Rounded" at 18.648,-65.1 h1.52
  text "r250_200h120_170r100z152m255_205p250_200" at 26.006,-65.1 h1.52
  text "1.700mm (66.93mil)" at 84.168,-65.1 h1.52
  text "0.500mm (19.69mil)" at 95.488,-65.1 h1.52
  text "4" at -26.198,-67.127 h1.52
  text "0.700mm (27.56mil)" at -20.393,-67.127 h1.52
  text "PTH" at -9.01,-67.127 h1.52
  text "Round" at -4.166,-67.127 h1.52
  text "TOP - Bottom" at 2.941,-67.127 h1.52
  text "Pad" at 12.802,-67.127 h1.52
  text "Rounded" at 18.648,-67.127 h1.52
  text "(Mixed)" at 26.006,-67.127 h1.52
  text "-" at 84.168,-67.127 h1.52
  text "-" at 95.488,-67.127 h1.52
  text "118" at -26.198,-69.153 h1.52
  text "1.000mm (39.37mil)" at -20.393,-69.153 h1.52
  text "PTH" at -9.01,-69.153 h1.52
  text "Round" at -4.166,-69.153 h1.52
  text "TOP - Bottom" at 2.941,-69.153 h1.52
  text "Pad" at 12.802,-69.153 h1.52
  text "Rounded" at 18.648,-69.153 h1.52
  text "(Mixed)" at 26.006,-69.153 h1.52
  text "-" at 84.168,-69.153 h1.52
  text "-" at 95.488,-69.153 h1.52
  text "493" at -26.198,-71.18 h1.52
  text "0.200mm (7.87mil)" at -20.393,-71.18 h1.52
  text "PTH" at -9.01,-71.18 h1.52
  text "Round" at -4.166,-71.18 h1.52
  text "TOP - Bottom" at 2.941,-71.18 h1.52
  text "Via" at 12.802,-71.18 h1.52
  text "Rounded" at 18.648,-71.18 h1.52
  text "(Mixed)" at 26.006,-71.18 h1.52
  text "-" at 84.168,-71.18 h1.52
  text "-" at 95.488,-71.18 h1.52
  text "626 Total" at -26.198,-73.206 h1.52
  text "Slot definitions :" at -31.733,-74.885 h1.52
  text "Routed Path Length" at -23.038,-74.885 h1.52
  text "= Calculated from tool start centre position to tool end centre position." at -12.6,-74.885 h1.52
  text "Hole Length" at -23.038,-75.957 h1.52
  text "= Routed Path Length + Tool Size = Slot length as defined in the PCB layout" at -16.54,-75.957 h1.52
  text "DRILL DRAWING" at -20,-91.8 h2.45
